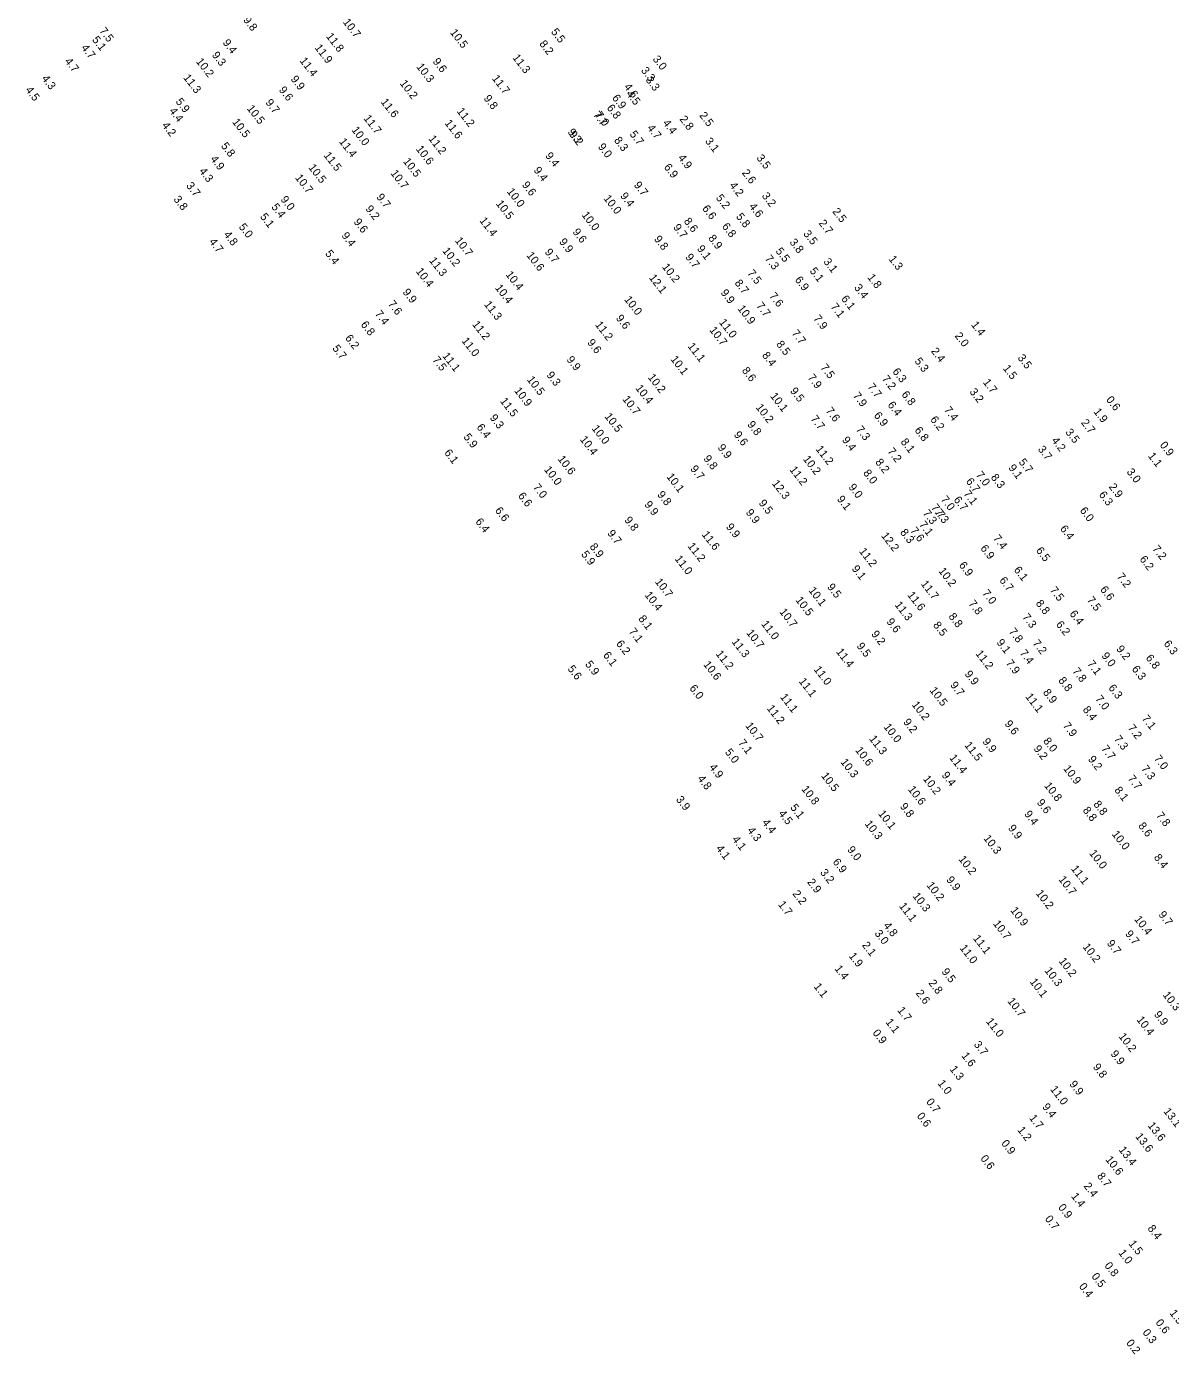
# Model space of a CAD drawing. Extents: x 815385 to 820851, y 582449 to 604245.
# Drawn here: x 817700 to 818415, y 594919 to 595749 of the extents above; entities that cross this region are included whole.
import ezdxf

# ---------------------------------------------------------------- set-up
doc = ezdxf.new("R2010")
doc.units = 0
for name, color, linetype in [('V-TOPO-SOUN-011609', 7, 'Continuous'), ('V-TOPO-SOUN-020509C', 7, 'Continuous'), ('V-TOPO-SOUN-EXCSS', 7, 'Continuous')]:
    doc.layers.add(name, color=color, linetype=linetype)

msp = doc.modelspace()

# ---------------------------------------------------------------- texts
at = {"layer": 'V-TOPO-SOUN-011609'}
for s, p in [('2.5', (818120.42, 595693.64)), ('4.7', (818087.81, 595685.75)), ('4.4', (818097.56, 595688.87)), ('2.8', (818108.05, 595691.32)), ('8.3', (818067.12, 595678.11)), ('5.7', (818076.85, 595681.91)), ('9.0', (818057.04, 595674.05)), ('3.5', (818156.12, 595667.07)), ('2.6', (818146.98, 595657.81)), ('5.2', (818130.75, 595642.12)), ('4.2', (818139.25, 595649.9)), ('6.6', (818122.17, 595635.45)), ('2.5', (818203.54, 595633.62)), ('8.6', (818110.7, 595627.49)), ('2.7', (818195.03, 595626.28)), ('9.7', (818104.09, 595623.7)), ('3.5', (818185.38, 595619.7)), ('5.5', (818168.05, 595608.84)), ('3.8', (818176.76, 595614.43)), ('7.3', (818161.36, 595604.14)), ('1.3', (818238.74, 595603.87)), ('7.5', (818150.44, 595595.07)), ('1.8', (818225.45, 595592.4)), ('8.7', (818142.46, 595588.89)), ('3.4', (818217.17, 595586.02)), ('9.9', (818133.72, 595582.86)), ('6.1', (818209.04, 595579.03)), ('7.9', (818191.72, 595566.75)), ('7.1', (818202.42, 595574.07)), ('1.4', (818290.28, 595562.79)), ('8.5', (818168.47, 595550.63)), ('7.7', (818178.08, 595557.48)), ('2.0', (818279.98, 595555.91)), ('8.4', (818159.6, 595543.72)), ('2.4', (818265.19, 595546.33)), ('3.5', (818319.3, 595542.15)), ('5.3', (818254.87, 595540.09)), ('1.5', (818310.11, 595535.59)), ('7.2', (818234.43, 595529.05)), ('6.3', (818241.07, 595533.59)), ('1.7', (818297.63, 595526.85)), ('7.9', (818216.39, 595518.48)), ('7.7', (818225.43, 595524.07)), ('3.2', (818289.23, 595520.95)), ('7.6', (818199.38, 595509.07)), ('7.4', (818273.32, 595509.61)), ('0.6', (818374.57, 595516.02)), ('7.7', (818189.93, 595504.03)), ('6.2', (818264.71, 595503.58)), ('2.7', (818358.93, 595501.67)), ('1.9', (818366.73, 595508.51)), ('6.8', (818254.87, 595496.87)), ('3.5', (818349.14, 595495.69)), ('7.2', (818237.95, 595483.72)), ('8.1', (818246.22, 595489.66)), ('3.7', (818331.92, 595485.04)), ('4.2', (818340.44, 595490.48)), ('0.9', (818408.09, 595487.66)), ('8.2', (818230.37, 595476.94)), ('5.7', (818319.95, 595477)), ('1.1', (818400.74, 595480.82)), ('8.0', (818222.79, 595470.19)), ('8.3', (818302.53, 595467.44)), ('9.1', (818313.53, 595473.42)), ('3.0', (818387.42, 595470.88)), ('2.9', (818376.24, 595461.56)), ('6.7', (818279.31, 595453.44)), ('7.1', (818285.45, 595457.2)), ('6.3', (818370.05, 595456.64)), ('7.3', (818267.53, 595445.59)), ('6.0', (818358.12, 595446.73)), ('7.6', (818252.16, 595434.13)), ('7.1', (818257.69, 595437.9)), ('6.4', (818345.79, 595435.37)), ('6.5', (818330.75, 595421.73)), ('7.2', (818403.47, 595422.83)), ('6.1', (818316.93, 595409.61)), ('6.2', (818395.49, 595416.29)), ('6.7', (818307.85, 595403.12)), ('7.2', (818381.26, 595405.43)), ('7.0', (818297.16, 595395.06)), ('6.6', (818370.84, 595397.38)), ('7.8', (818288.6, 595388.52)), ('7.5', (818362.58, 595390.79)), ('6.4', (818351.73, 595382.19)), ('6.2', (818343.24, 595375.56)), ('7.2', (818328.65, 595363.79)), ('6.3', (818410.52, 595363.52)), ('7.9', (818311.9, 595351.39)), ('7.4', (818320.58, 595357.64)), ('6.8', (818399.32, 595354.6)), ('6.3', (818390.64, 595347.68)), ('6.3', (818375.99, 595335.9)), ('7.0', (818367.77, 595329.02)), ('8.4', (818359.96, 595322.32)), ('7.9', (818347.53, 595312.26)), ('7.3', (818396.5, 595285.35)), ('7.0', (818404.5, 595291.71)), ('7.7', (818388.07, 595279.2)), ('8.1', (818379.75, 595272)), ('8.4', (818404.41, 595229.9))]:
    msp.add_text(s, height=5, rotation=307.782, dxfattribs=at).set_placement(p)
at = {"layer": 'V-TOPO-SOUN-020509C'}
for s, p in [('9.8', (817835.41, 595753.27)), ('10.7 ', (817897.73, 595751.99)), ('5.1', (817740.99, 595740.96)), ('7.5', (817745.57, 595746.45)), ('11.8 ', (817887.2, 595743.07)), ('10.5 ', (817964.64, 595745.49)), ('5.5', (818027.74, 595745.9)), ('4.7', (817734.17, 595735.91)), ('9.4', (817822.6, 595739.11)), ('11.9 ', (817880.09, 595735.97)), ('8.2', (818020.43, 595738.39)), ('4.7', (817723.86, 595727.48)), ('10.2 ', (817805.93, 595727.35)), ('9.3', (817815.86, 595731.37)), ('11.4 ', (817870.72, 595727.81)), ('9.6', (817953.82, 595727.34)), ('11.3 ', (818003.69, 595729.75)), ('3.0', (818091.25, 595728.87)), ('11.3 ', (817798, 595717.26)), ('9.9', (817865.08, 595716.36)), ('10.3 ', (817943.63, 595724.07)), ('11.7 ', (817990.87, 595716.76)), ('3.3', (818084, 595721.78)), ('4.5', (817699.33, 595709.55)), ('4.3', (817709.47, 595716.72)), ('9.6', (817857.7, 595709.59)), ('10.2 ', (817933.26, 595713.66)), ('4.6', (818073.3, 595711.45)), ('5.9', (817793.2, 595702.25)), ('9.7', (817849.32, 595701.7)), ('11.6 ', (817921.38, 595702.09)), ('9.8', (817985.66, 595704.27)), ('6.9', (818065.93, 595704.57)), ('4.4', (817789.16, 595696.41)), ('10.5 ', (817837.72, 595697.98)), ('11.7 ', (817910.64, 595691.82)), ('11.2 ', (817968.87, 595696.27)), ('7.7', (818053.98, 595694.09)), ('4.2', (817784.61, 595687.43)), ('10.5 ', (817828.55, 595689.57)), ('10.0 ', (817903.14, 595684.57)), ('11.6 ', (817961.29, 595688.83)), ('5.8', (817821.52, 595674.61)), ('11.4 ', (817895.28, 595677.28)), ('11.2 ', (817951.17, 595679.11)), ('9.2', (818039.04, 595681.79)), ('11.5 ', (817885.69, 595668.69)), ('10.6 ', (817943.34, 595672.65)), ('9.4', (818024.12, 595668.44)), ('4.9', (817814.87, 595666.37)), ('10.5 ', (817876.2, 595661.1)), ('10.5 ', (817935.32, 595664.93)), ('9.4', (818016.88, 595659.35)), ('4.3', (817807.84, 595658.79)), ('10.7 ', (817867.85, 595654.7)), ('10.7 ', (817927.49, 595657.5)), ('9.6', (818009.57, 595650.25)), ('3.7', (817799.8, 595649.76)), ('9.7', (817918.65, 595642.6)), ('10.0 ', (818000.17, 595646.1)), ('9.4', (818070.98, 595643.36)), ('3.8', (817791.88, 595641.23)), ('5.4', (817853.01, 595636.45)), ('9.0', (817858.75, 595641.16)), ('9.2', (817911.8, 595635.24)), ('10.5 ', (817993.32, 595638.51)), ('10.0 ', (818060.59, 595641.79)), ('5.1', (817845.93, 595630.36)), ('9.6', (817904.44, 595627.08)), ('11.4 ', (817983.06, 595627.91)), ('10.0 ', (818046.9, 595631.45)), ('4.8', (817823.19, 595619.18)), ('5.0', (817832.64, 595623.98)), ('9.4', (817896.83, 595618.54)), ('9.6', (818041.18, 595620.83)), ('4.7', (817814.1, 595614.67)), ('10.2 ', (817959.84, 595609.03)), ('10.7 ', (817967.71, 595615.44)), ('9.9', (818032.8, 595614.68)), ('5.4', (817886.61, 595607.35)), ('11.3 ', (817951.6, 595602.96)), ('10.6 ', (818012.41, 595606.18)), ('9.7', (818023.83, 595608.22)), ('10.4 ', (817943.31, 595596.21)), ('10.4 ', (817999.37, 595594.22)), ('12.1 ', (818088.97, 595592.21)), ('10.2 ', (818097.12, 595598.99)), ('10.4 ', (817992.78, 595585.9)), ('7.6', (817925.86, 595575.81)), ('9.9', (817935.05, 595583.2)), ('11.3 ', (817985.93, 595575.55)), ('10.0 ', (818073.5, 595578.64)), ('7.4', (817917.69, 595569.65)), ('9.6', (818068.27, 595566.95)), ('6.8', (817908.88, 595562.93)), ('11.2 ', (817978.52, 595563.09)), ('11.2 ', (818055.29, 595562.83)), ('10.7 ', (818126.69, 595559.54)), ('11.0 ', (818132.73, 595564.37)), ('6.2', (817899.07, 595554.47)), ('11.0 ', (817971.9, 595552.79)), ('9.6', (818050.37, 595551.72)), ('5.7', (817891.13, 595548.08)), ('11.1 ', (817959.85, 595543.37)), ('11.1 ', (818113.08, 595549.44)), ('7.5', (817953.66, 595540.86)), ('9.9', (818037.43, 595541.07)), ('10.1 ', (818102.45, 595541.33)), ('10.5 ', (818012.7, 595528.57)), ('9.3', (818024.9, 595531.41)), ('10.2 ', (818088.26, 595529.95)), ('10.9 ', (818004.75, 595521.65)), ('10.4 ', (818080.48, 595523.2)), ('10.1 ', (818164.73, 595518.25)), ('11.5 ', (817995.91, 595515.12)), ('10.7 ', (818072.38, 595516.33)), ('10.2 ', (818155.68, 595511.21)), ('9.3', (817989.47, 595504.71)), ('10.5 ', (818061.17, 595505.51)), ('5.9', (817973.04, 595492.7)), ('6.4', (817981.23, 595498.76)), ('10.0 ', (818053.18, 595498.02)), ('9.6', (818141.95, 595494.09)), ('9.8', (818150.39, 595500.5)), ('10.4 ', (818045.82, 595491.19)), ('9.9', (818131.83, 595486.07)), ('11.2 ', (818193.09, 595485.13)), ('6.1', (817961.03, 595482.86)), ('10.6 ', (818031.91, 595478.95)), ('9.8', (818122.97, 595479.18)), ('10.2 ', (818185.19, 595478.9)), ('10.0 ', (818023.38, 595472.36)), ('10.1 ', (818099.92, 595467.86)), ('9.7', (818114.76, 595472.8)), ('11.2 ', (818176.8, 595472.28)), ('7.0', (818016.45, 595461.29)), ('12.3 ', (818165.79, 595463.65)), ('6.6', (818007.1, 595455.9)), ('9.8', (818094.1, 595456.74)), ('9.5', (818157.54, 595451.36)), ('6.6', (817992.74, 595446.75)), ('9.9', (818086.06, 595450.49)), ('9.9', (818149.42, 595445.47)), ('6.4', (817980.48, 595439.8)), ('9.8', (818073.59, 595440.79)), ('9.9', (818137.05, 595436.52)), ('9.7', (818062.93, 595432.5)), ('11.6 ', (818121.96, 595431.74)), ('12.2 ', (818234.08, 595430.97)), ('5.9', (818046.55, 595419.4)), ('8.9', (818051.84, 595424.12)), ('11.2 ', (818113.09, 595424.52)), ('11.2 ', (818220.23, 595421.28)), ('11.0 ', (818105.05, 595416.52)), ('9.1', (818215.66, 595410.34)), ('10.7 ', (818092.71, 595402.21)), ('10.4 ', (818086.24, 595393.92)), ('10.1 ', (818188.68, 595396.8)), ('9.5', (818200.26, 595398.95)), ('11.6 ', (818250.41, 595393.95)), ('11.7 ', (818258.84, 595400.89)), ('10.5 ', (818180.52, 595390.77)), ('11.3 ', (818242.48, 595387.76)), ('8.1', (818082.34, 595379.12)), ('10.7 ', (818170.43, 595383.42)), ('9.6', (818237.34, 595377.24)), ('7.1', (818076.34, 595371.12)), ('10.7 ', (818149.78, 595370.27)), ('11.0 ', (818159.12, 595375.8)), ('9.2', (818227.84, 595369.53)), ('6.2', (818068.43, 595363.53)), ('11.3 ', (818140.64, 595364.71)), ('9.5', (818218.7, 595362.05)), ('6.1', (818060.26, 595356.32)), ('11.2 ', (818130.66, 595357.15)), ('11.4 ', (818205.88, 595358.46)), ('11.2 ', (818292.98, 595357.3)), ('5.6', (818038.08, 595347.82)), ('5.9', (818049.06, 595350.66)), ('10.6 ', (818122.92, 595350.54)), ('11.0 ', (818191.92, 595347.44)), ('9.9', (818286.19, 595344.55)), ('6.0', (818114.23, 595335.67)), ('11.1 ', (818182.55, 595340)), ('9.7', (818277.15, 595337.66)), ('11.1 ', (818170.89, 595330.2)), ('10.5 ', (818264.32, 595334.34)), ('11.2 ', (818162.59, 595323.09)), ('10.2 ', (818253.17, 595325.41)), ('10.7 ', (818149.2, 595312.23)), ('10.0 ', (818235.57, 595311.5)), ('9.2', (818247.78, 595314.52)), ('9.6', (818311.17, 595313.45)), ('7.1', (818144.71, 595301.52)), ('11.3 ', (818226.53, 595304.07)), ('9.9', (818297.3, 595302.32)), ('5.0', (818136.38, 595295.71)), ('10.6 ', (818217.86, 595296.93)), ('11.5 ', (818286.05, 595300.07)), ('4.9', (818126.54, 595286.31)), ('10.3 ', (818208.61, 595289.57)), ('11.4 ', (818276.63, 595292.2)), ('10.9 ', (818347.83, 595285.48)), ('4.8', (818119.23, 595279.16)), ('10.5 ', (818196.56, 595280.96)), ('10.2 ', (818260.17, 595279.05)), ('9.4', (818271.83, 595281.33)), ('10.8 ', (818184.21, 595272.68)), ('10.6 ', (818250.77, 595272.5)), ('10.8 ', (818335.87, 595274.8)), ('3.9', (818105.84, 595266.16)), ('5.1', (818177.23, 595261.12)), ('9.8', (818245.73, 595261.81)), ('9.6', (818331.27, 595264.22)), ('4.5', (818169.82, 595257.34)), ('10.1 ', (818232.15, 595257.28)), ('9.4', (818323.43, 595257.04)), ('4.3', (818150.35, 595246.86)), ('4.4', (818159.58, 595251.76)), ('10.3 ', (818223.77, 595250.96)), ('9.9', (818313.31, 595248.22)), ('10.0 ', (818378.18, 595244.5)), ('4.1', (818140.88, 595241.23)), ('10.3 ', (818297.95, 595241.9)), ('4.1', (818130.82, 595235.53)), ('6.9', (818203.74, 595227.11)), ('9.0', (818212.79, 595234.82)), ('10.2 ', (818282.38, 595228.87)), ('10.0 ', (818364, 595232.57)), ('3.2', (818195.87, 595220.56)), ('11.1 ', (818352.66, 595222.88)), ('2.9', (818187.81, 595214.55)), ('10.2 ', (818262.42, 595212.54)), ('9.9', (818274.71, 595215.98)), ('10.7 ', (818344.88, 595216.21)), ('2.2', (818178.62, 595207.27)), ('10.3 ', (818253.67, 595205.82)), ('10.2 ', (818330.65, 595207.54)), ('1.7', (818169.64, 595200.55)), ('11.1 ', (818245.19, 595199.57)), ('10.9 ', (818314.78, 595196.85)), ('9.7', (818407.31, 595194.23)), ('4.8', (818235.41, 595187.36)), ('10.7 ', (818303.95, 595188.52)), ('10.4 ', (818392.18, 595191.33)), ('3.0', (818229.89, 595182.49)), ('11.1 ', (818291.44, 595179.4)), ('9.7', (818386.46, 595182.19)), ('2.1', (818222.06, 595175.12)), ('11.0 ', (818283.11, 595173.33)), ('10.2 ', (818359.94, 595174.09)), ('9.7', (818375.03, 595176.23)), ('1.9', (818213.8, 595168.35)), ('10.2 ', (818344.99, 595165.14)), ('1.4', (818204.91, 595160.44)), ('9.5', (818271.75, 595158.54)), ('10.3 ', (818336.09, 595159.24)), ('1.1', (818191.89, 595149.27)), ('2.6', (818255.66, 595145.11)), ('2.8', (818263.6, 595151.46)), ('10.1 ', (818326.89, 595152.24)), ('10.3 ', (818410, 595144.03)), ('10.7 ', (818312.95, 595140.11)), ('1.7', (818244.14, 595134.43)), ('11.0 ', (818299.54, 595127.46)), ('10.4 ', (818393.61, 595128.55)), ('9.9', (818404.51, 595131.8)), ('0.9', (818228.66, 595120.3)), ('1.1', (818236.78, 595127.03)), ('3.7', (818291.89, 595113.04)), ('10.2 ', (818382.4, 595118.09)), ('1.6', (818284.21, 595106.01)), ('9.9', (818377.35, 595107.19)), ('1.3', (818276.85, 595097.64)), ('9.8', (818366.31, 595099)), ('1.0', (818269.29, 595088.77)), ('9.9', (818351.63, 595088.24)), ('11.0 ', (818339.63, 595085.09)), ('0.7', (818262.13, 595077.19)), ('9.4', (818334.65, 595074.11)), ('13.1 ', (818410.42, 595071.27)), ('0.6', (818256.33, 595068.33)), ('1.7', (818326.51, 595067.12)), ('13.6 ', (818400.56, 595062.42)), ('1.2', (818319.17, 595059.64)), ('13.6 ', (818392.83, 595055.56)), ('0.9', (818309.06, 595051.23)), ('13.4 ', (818382.47, 595047.22)), ('0.6', (818296.05, 595041.81)), ('10.6 ', (818374.15, 595041.18)), ('8.7', (818368.93, 595030.83)), ('2.4', (818360.58, 595024.56)), ('0.9', (818344.6, 595011.23)), ('1.4', (818352.71, 595018.22)), ('0.7', (818336.34, 595004.06)), ('8.4', (818400.46, 594998.07)), ('1.5', (818388.65, 594988.55)), ('1.0', (818382.27, 594982.82)), ('0.8', (818373.54, 594974.87)), ('0.4', (818357.59, 594961.83)), ('0.5', (818365.42, 594968.12)), ('1.5', (818414.23, 594945.18)), ('0.6', (818405.47, 594939.21)), ('0.3', (818397.33, 594933.06)), ('0.2', (818387.12, 594926.51))]:
    msp.add_text(s, height=5, rotation=307.782, dxfattribs=at).set_placement(p)
at = {"layer": 'V-TOPO-SOUN-EXCSS'}
for s, p in [('3.3', (818086.84, 595715.79)), ('4.5', (818074.71, 595706.98)), ('7.0', (818055.3, 595693.84)), ('6.8', (818062.57, 595698.35)), ('9.3', (818038.11, 595683.25)), ('3.1', (818124.02, 595677.58)), ('6.9', (818098.25, 595661.33)), ('4.9', (818107.06, 595667.1)), ('9.7', (818079.48, 595650.15)), ('3.2', (818159.44, 595643.38)), ('4.6', (818151.43, 595636.78)), ('5.8', (818143.33, 595630.43)), ('8.9', (818125.95, 595616.88)), ('6.8', (818134.56, 595624.29)), ('9.8', (818092.14, 595616.38)), ('9.1', (818118.91, 595610.38)), ('9.7', (818111.7, 595605.07)), ('3.1', (818197.96, 595602.25)), ('5.1', (818189.36, 595596.46)), ('6.9', (818180.09, 595590.89)), ('7.6', (818164.11, 595580.84)), ('10.9 ', (818144.3, 595572.92)), ('7.7', (818156.01, 595574.68)), ('8.6', (818147, 595534.2)), ('7.5', (818196.14, 595536.07)), ('7.9', (818188.1, 595529.82)), ('9.5', (818177.11, 595521.46)), ('6.8', (818246.69, 595519.25)), ('6.4', (818238.05, 595512.75)), ('6.9', (818229.46, 595506.16)), ('7.3', (818218.3, 595497.42)), ('9.4', (818209.54, 595490.81)), ('7.0', (818293.19, 595468.98)), ('9.0', (818213.62, 595461.3)), ('6.7', (818286.95, 595464.93)), ('9.1', (818206.38, 595453.86)), ('7.0', (818271.25, 595453.66)), ('7.3', (818260.06, 595445.04)), ('7.7', (818265.25, 595448.59)), ('8.3', (818245.86, 595433.07)), ('7.4', (818303.97, 595429.4)), ('6.9', (818296.01, 595423.14)), ('6.9', (818282.6, 595412.53)), ('10.2 ', (818269.83, 595408.95)), ('7.5', (818339.46, 595396.98)), ('8.8', (818330.61, 595388.69)), ('8.8', (818276.1, 595380.51)), ('7.3', (818322.22, 595380.16)), ('8.5', (818266.46, 595375.14)), ('7.8', (818313.8, 595371.08)), ('9.1', (818306.12, 595364.26)), ('9.2', (818380.93, 595360.23)), ('7.1', (818362.79, 595350.91)), ('9.0', (818371.68, 595355.97)), ('7.8', (818353.53, 595346.36)), ('8.8', (818344.7, 595340.52)), ('11.1 ', (818324.15, 595330.38)), ('8.9', (818335.1, 595333.09)), ('7.2', (818388.09, 595310.81)), ('7.1', (818396.92, 595316.76)), ('8.0', (818335.24, 595302.68)), ('7.3', (818379.49, 595303.97)), ('9.2', (818329.26, 595297.89)), ('7.7', (818371.53, 595297.86)), ('9.2', (818363.28, 595291.3)), ('8.8', (818366.61, 595263.19)), ('8.8', (818359.97, 595259.41)), ('7.8', (818405.83, 595256.19)), ('8.6', (818394.63, 595249.7))]:
    msp.add_text(s, height=5, rotation=307.782, dxfattribs=at).set_placement(p)

doc.saveas('drawing.dxf')
